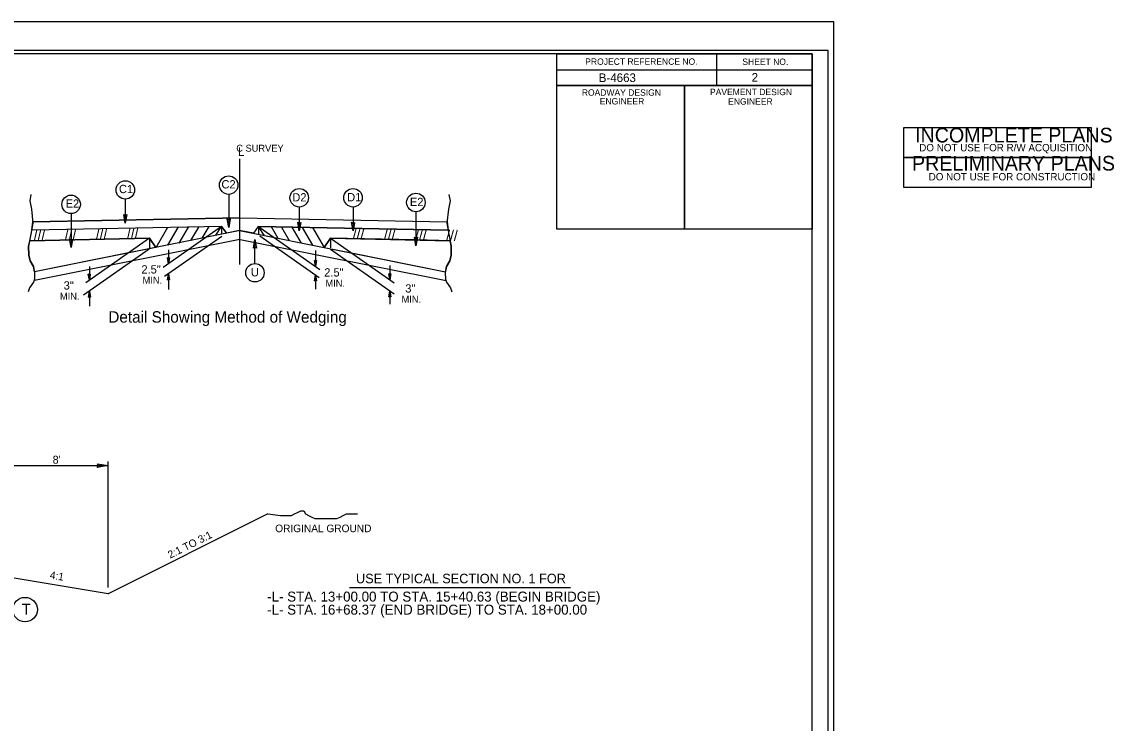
# Model space of a CAD drawing. Extents: x 693533 to 693723, y 486383 to 486493.
# Drawn here: x 693637.4 to 693723, y 486438.3 to 486493.3 of the extents above; entities that cross this region are included whole.
import ezdxf

# ---------------------------------------------------------------- set-up
doc = ezdxf.new("R2010")
doc.units = 0
for name, color, linetype in [('Old_Level_1', 7, 'Continuous'), ('Old_Level_11', 7, 'Continuous'), ('Old_Level_20', 7, 'Continuous'), ('Old_Level_21', 7, 'Continuous'), ('Old_Level_28', 7, 'Continuous'), ('Prop Dimension', 7, 'Continuous'), ('Sheet Cutting Line CELL', 7, 'Continuous'), ('Sheet Data Field CELL', 7, 'Continuous'), ('Sheet Plot Border Inside CELL', 7, 'Continuous'), ('Sheet Plot Border Outside CELL', 7, 'Continuous'), ('Sheet Sticker Incomplete CELL', 7, 'Continuous'), ('Sheet Sticker Preliminary CELL', 7, 'Continuous'), ('Sheet Typical CELL', 7, 'Continuous'), ('Typical Hinge Slope Arterial CELL', 7, 'Continuous'), ('Typical ID Circle CELL', 7, 'Continuous'), ('Typical Text ID Circle CELL', 7, 'Continuous'), ('Typical Text Label CELL', 7, 'Continuous')]:
    doc.layers.add(name, color=color, linetype=linetype)

msp = doc.modelspace()

# ---------------------------------------------------------------- linework, layer by layer
at = {"layer": 'Old_Level_1'}
for p, q in [((693648.814, 486477.181), (693647.891, 486475.6)), ((693649.624, 486477.198), (693648.807, 486475.796)), ((693650.426, 486477.214), (693649.693, 486475.957)), ((693651.234, 486477.212), (693650.627, 486476.171)), ((693652.049, 486477.254), (693651.519, 486476.346)), ((693656.057, 486477.18), (693660.77, 486473.879)), ((693656.944, 486477.254), (693657.474, 486476.346)), ((693657.759, 486477.212), (693658.366, 486476.171)), ((693658.567, 486477.214), (693659.3, 486475.957)), ((693659.369, 486477.198), (693660.186, 486475.796)), ((693660.18, 486477.181), (693661.089, 486475.623)), ((693647.394, 486476.339), (693638.01, 486476.151)), ((693638.01, 486476.151), (693647.394, 486476.339)), ((693654.49, 486476.253), (693638.377, 486473.029)), ((693647.394, 486476.339), (693642.411, 486472.85)), ((693647.904, 486475.622), (693647.394, 486476.339)), ((693647.394, 486476.339), (693647.394, 486475.52)), ((693647.394, 486476.339), (693647.903, 486475.623)), ((693653.064, 486476.472), (693648.588, 486473.337)), ((693654.503, 486476.253), (693670.654, 486473.022)), ((693656.05, 486476.538), (693660.717, 486473.271)), ((693661.599, 486476.339), (693661.089, 486475.623)), ((693661.09, 486475.623), (693661.599, 486476.339)), ((693661.599, 486476.339), (693670.984, 486476.151)), ((693661.599, 486476.339), (693661.599, 486475.578)), ((693668.292, 486476.205), (693661.599, 486476.339)), ((693661.675, 486476.286), (693666.589, 486472.844)), ((693647.39, 486475.495), (693642.239, 486471.87)), ((693647.394, 486475.521), (693645.76, 486475.194)), ((693647.903, 486475.623), (693647.394, 486475.521)), ((693648.896, 486475.431), (693648.896, 486474.343)), ((693660.425, 486475.369), (693660.425, 486474.121)), ((693661.089, 486475.623), (693663.234, 486475.194)), ((693661.599, 486475.479), (693666.581, 486471.989)), ((693670.984, 486476.151), (693668.292, 486476.205)), ((693645.76, 486475.194), (693638.382, 486473.719)), ((693648.896, 486474.343), (693648.811, 486474.82)), ((693648.896, 486474.758), (693648.811, 486474.82)), ((693648.896, 486474.343), (693648.823, 486474.811)), ((693648.835, 486474.802), (693648.896, 486474.343)), ((693648.896, 486474.343), (693648.847, 486474.794)), ((693648.86, 486474.785), (693648.896, 486474.343)), ((693648.896, 486474.343), (693648.872, 486474.776)), ((693648.884, 486474.767), (693648.896, 486474.343)), ((693648.896, 486474.343), (693648.98, 486474.82)), ((693648.98, 486474.82), (693648.896, 486474.758)), ((693648.968, 486474.811), (693648.896, 486474.343)), ((693648.896, 486474.343), (693648.955, 486474.802)), ((693648.943, 486474.794), (693648.896, 486474.343)), ((693648.896, 486474.343), (693648.931, 486474.785)), ((693648.919, 486474.776), (693648.896, 486474.343)), ((693648.896, 486474.343), (693648.908, 486474.767)), ((693648.896, 486474.758), (693648.896, 486474.343)), ((693660.425, 486474.121), (693660.341, 486474.599)), ((693660.425, 486474.537), (693660.341, 486474.599)), ((693660.425, 486474.121), (693660.353, 486474.59)), ((693660.365, 486474.581), (693660.425, 486474.121)), ((693660.425, 486474.121), (693660.377, 486474.572)), ((693660.389, 486474.563), (693660.425, 486474.121)), ((693660.425, 486474.121), (693660.401, 486474.554)), ((693660.413, 486474.546), (693660.425, 486474.121)), ((693660.425, 486474.121), (693660.51, 486474.599)), ((693660.51, 486474.599), (693660.425, 486474.537)), ((693660.497, 486474.59), (693660.425, 486474.121)), ((693660.425, 486474.121), (693660.485, 486474.581)), ((693660.473, 486474.572), (693660.425, 486474.121)), ((693660.425, 486474.121), (693660.461, 486474.563)), ((693660.449, 486474.554), (693660.425, 486474.121)), ((693660.425, 486474.121), (693660.437, 486474.546)), ((693660.425, 486474.537), (693660.425, 486474.121)), ((693663.234, 486475.194), (693670.611, 486473.719)), ((693642.692, 486474.131), (693642.692, 486473.046)), ((693666.252, 486474.209), (693666.252, 486473.081)), ((693642.692, 486473.046), (693642.607, 486473.523)), ((693642.692, 486473.462), (693642.607, 486473.523)), ((693642.692, 486473.046), (693642.619, 486473.515)), ((693642.632, 486473.505), (693642.692, 486473.046)), ((693642.692, 486473.046), (693642.644, 486473.497)), ((693642.656, 486473.488), (693642.692, 486473.046)), ((693642.692, 486473.046), (693642.668, 486473.479)), ((693642.68, 486473.471), (693642.692, 486473.046)), ((693642.692, 486473.046), (693642.776, 486473.523)), ((693642.776, 486473.523), (693642.692, 486473.462)), ((693642.764, 486473.515), (693642.692, 486473.046)), ((693642.692, 486473.046), (693642.752, 486473.505)), ((693642.74, 486473.497), (693642.692, 486473.046)), ((693642.692, 486473.046), (693642.728, 486473.488)), ((693642.716, 486473.479), (693642.692, 486473.046)), ((693642.692, 486473.046), (693642.704, 486473.471)), ((693642.692, 486473.462), (693642.692, 486473.046)), ((693648.896, 486473.553), (693648.811, 486473.075)), ((693648.811, 486473.075), (693648.896, 486473.137)), ((693648.823, 486473.085), (693648.896, 486473.553)), ((693648.896, 486473.553), (693648.835, 486473.093)), ((693648.847, 486473.103), (693648.896, 486473.553)), ((693648.896, 486473.553), (693648.86, 486473.111)), ((693648.872, 486473.12), (693648.896, 486473.553)), ((693648.896, 486473.553), (693648.884, 486473.129)), ((693648.896, 486473.553), (693648.896, 486472.327)), ((693648.896, 486473.553), (693648.98, 486473.075)), ((693648.896, 486473.137), (693648.896, 486473.553)), ((693648.908, 486473.129), (693648.896, 486473.553)), ((693648.896, 486473.553), (693648.919, 486473.12)), ((693648.931, 486473.111), (693648.896, 486473.553)), ((693648.896, 486473.553), (693648.943, 486473.103)), ((693648.955, 486473.093), (693648.896, 486473.553)), ((693648.896, 486473.553), (693648.968, 486473.085)), ((693648.896, 486473.137), (693648.98, 486473.075)), ((693660.425, 486473.475), (693660.341, 486472.998)), ((693660.341, 486472.998), (693660.425, 486473.06)), ((693660.353, 486473.007), (693660.425, 486473.475)), ((693660.425, 486473.475), (693660.365, 486473.016)), ((693660.377, 486473.025), (693660.425, 486473.475)), ((693660.425, 486473.475), (693660.389, 486473.034)), ((693660.401, 486473.042), (693660.425, 486473.475)), ((693660.425, 486473.475), (693660.413, 486473.051)), ((693660.425, 486473.475), (693660.425, 486472.359)), ((693660.425, 486473.475), (693660.51, 486472.998)), ((693660.425, 486473.06), (693660.425, 486473.475)), ((693660.437, 486473.051), (693660.425, 486473.475)), ((693660.425, 486473.475), (693660.449, 486473.042)), ((693660.461, 486473.034), (693660.425, 486473.475)), ((693660.425, 486473.475), (693660.473, 486473.025)), ((693660.485, 486473.016), (693660.425, 486473.475)), ((693660.425, 486473.475), (693660.497, 486473.007)), ((693660.425, 486473.06), (693660.51, 486472.998)), ((693666.252, 486473.081), (693666.167, 486473.558)), ((693666.252, 486473.497), (693666.167, 486473.558)), ((693666.252, 486473.081), (693666.179, 486473.549)), ((693666.191, 486473.541), (693666.252, 486473.081)), ((693666.252, 486473.081), (693666.203, 486473.533)), ((693666.215, 486473.523), (693666.252, 486473.081)), ((693666.252, 486473.081), (693666.227, 486473.515)), ((693666.239, 486473.505), (693666.252, 486473.081)), ((693666.252, 486473.081), (693666.336, 486473.558)), ((693666.336, 486473.558), (693666.252, 486473.497)), ((693666.323, 486473.549), (693666.252, 486473.081)), ((693666.252, 486473.081), (693666.311, 486473.541)), ((693666.299, 486473.533), (693666.252, 486473.081)), ((693666.252, 486473.081), (693666.287, 486473.523)), ((693666.275, 486473.515), (693666.252, 486473.081)), ((693666.252, 486473.081), (693666.263, 486473.505)), ((693666.252, 486473.497), (693666.252, 486473.081)), ((693642.692, 486472.187), (693642.607, 486471.71)), ((693642.62, 486471.719), (693642.692, 486472.187)), ((693642.692, 486472.187), (693642.632, 486471.728)), ((693642.644, 486471.737), (693642.692, 486472.187)), ((693642.692, 486472.187), (693642.656, 486471.746)), ((693642.668, 486471.754), (693642.692, 486472.187)), ((693642.692, 486472.187), (693642.68, 486471.762)), ((693642.692, 486472.187), (693642.692, 486471.027)), ((693642.692, 486472.187), (693642.776, 486471.71)), ((693642.692, 486471.772), (693642.692, 486472.187)), ((693642.704, 486471.762), (693642.692, 486472.187)), ((693642.692, 486472.187), (693642.716, 486471.754)), ((693642.728, 486471.746), (693642.692, 486472.187)), ((693642.692, 486472.187), (693642.74, 486471.737)), ((693642.752, 486471.728), (693642.692, 486472.187)), ((693642.692, 486472.187), (693642.764, 486471.719)), ((693666.252, 486472.221), (693666.167, 486471.743)), ((693666.179, 486471.752), (693666.252, 486472.221)), ((693666.252, 486472.221), (693666.191, 486471.761)), ((693666.203, 486471.77), (693666.252, 486472.221)), ((693666.252, 486472.221), (693666.215, 486471.779)), ((693666.227, 486471.788), (693666.252, 486472.221)), ((693666.252, 486472.221), (693666.239, 486471.796)), ((693666.252, 486472.221), (693666.252, 486471.173)), ((693666.252, 486472.221), (693666.336, 486471.743)), ((693666.252, 486471.806), (693666.252, 486472.221)), ((693666.263, 486471.796), (693666.252, 486472.221)), ((693666.252, 486472.221), (693666.275, 486471.788)), ((693666.287, 486471.779), (693666.252, 486472.221)), ((693666.252, 486472.221), (693666.299, 486471.77)), ((693666.311, 486471.761), (693666.252, 486472.221)), ((693666.252, 486472.221), (693666.323, 486471.752)), ((693642.607, 486471.71), (693642.692, 486471.772)), ((693642.692, 486471.772), (693642.776, 486471.71)), ((693666.167, 486471.743), (693666.252, 486471.806)), ((693666.252, 486471.806), (693666.336, 486471.743))]:
    msp.add_line(p, q, dxfattribs=at)
for points in [[(693638.109, 486479.764), (693638.023, 486479.288), (693638.153, 486478.612), (693638.268, 486477.517), (693638.109, 486476.653), (693637.923, 486475.717), (693637.937, 486475.011), (693638.052, 486474.565), (693638.312, 486474.118), (693638.398, 486473.629), (693638.383, 486473.139), (693638.297, 486472.908), (693637.995, 486472.447), (693637.894, 486472.131)], [(693670.883, 486479.764), (693670.97, 486479.288), (693670.84, 486478.612), (693670.725, 486477.517), (693670.883, 486476.653), (693671.071, 486475.717), (693671.056, 486475.011), (693670.941, 486474.565), (693670.682, 486474.118), (693670.596, 486473.629), (693670.609, 486473.139), (693670.696, 486472.908), (693670.998, 486472.447), (693671.099, 486472.131)], [(693638.382, 486473.719), (693638.312, 486474.118), (693638.052, 486474.565), (693637.937, 486475.011), (693637.923, 486475.717), (693638.009, 486476.151)], [(693670.611, 486473.719), (693670.682, 486474.118), (693670.941, 486474.565), (693671.056, 486475.011), (693671.071, 486475.717), (693670.984, 486476.151)]]:
    msp.add_lwpolyline(points, dxfattribs=at)
at = {"layer": 'Old_Level_11'}
for p, q in [((693654.497, 486474.291), (693654.497, 486482.563)), ((693653.615, 486479.786), (693653.615, 486477.182)), ((693654.497, 486474.291), (693654.497, 486479.941)), ((693645.507, 486479.406), (693645.507, 486477.532)), ((693659.143, 486478.79), (693659.143, 486476.916)), ((693663.361, 486478.79), (693663.361, 486476.916)), ((693654.496, 486477.945), (693638.261, 486477.621)), ((693638.261, 486477.621), (693654.496, 486477.945)), ((693641.256, 486478.274), (693641.256, 486475.609)), ((693654.496, 486477.945), (693670.733, 486477.621)), ((693654.498, 486477.945), (693670.733, 486477.621)), ((693668.292, 486478.422), (693668.292, 486475.757)), ((693638.168, 486476.969), (693638.261, 486477.621)), ((693653.072, 486477.267), (693638.168, 486476.969)), ((693653.072, 486477.267), (693638.168, 486476.969)), ((693653.053, 486477.255), (693648.479, 486474.051)), ((693652.611, 486476.572), (693653.051, 486477.261)), ((693653.051, 486477.261), (693653.051, 486476.695)), ((693653.437, 486476.732), (693653.072, 486477.267)), ((693653.072, 486477.249), (693653.437, 486476.732)), ((693655.933, 486477.267), (693655.556, 486476.732)), ((693655.933, 486477.267), (693655.556, 486476.732)), ((693655.909, 486477.255), (693655.932, 486477.254)), ((693655.933, 486477.267), (693670.826, 486476.969)), ((693670.826, 486476.969), (693655.933, 486477.267)), ((693656.383, 486476.572), (693655.942, 486477.261)), ((693655.942, 486477.261), (693655.942, 486476.638)), ((693670.733, 486477.621), (693670.826, 486476.969)), ((693654.521, 486476.947), (693638.382, 486473.719)), ((693654.472, 486476.947), (693653.437, 486476.732)), ((693654.472, 486476.947), (693670.611, 486473.719)), ((693655.556, 486476.732), (693654.472, 486476.947)), ((693655.671, 486474.362), (693655.671, 486476.236))]:
    msp.add_line(p, q, dxfattribs=at)
for points in [[(693645.622, 486478.204), (693645.507, 486477.532), (693645.387, 486478.207), (693645.507, 486478.122)], [(693653.731, 486477.854), (693653.615, 486477.182), (693653.496, 486477.858), (693653.615, 486477.772)], [(693659.258, 486477.587), (693659.143, 486476.916), (693659.023, 486477.591), (693659.143, 486477.505)], [(693663.477, 486477.587), (693663.361, 486476.916), (693663.242, 486477.591), (693663.361, 486477.505)], [(693641.372, 486476.28), (693641.256, 486475.609), (693641.137, 486476.284), (693641.256, 486476.198)], [(693655.556, 486475.565), (693655.671, 486476.236), (693655.791, 486475.561), (693655.671, 486475.647)], [(693668.407, 486476.429), (693668.292, 486475.757), (693668.172, 486476.432), (693668.292, 486476.347)]]:
    msp.add_lwpolyline(points, close=True, dxfattribs=at)
for centre in [(693645.507, 486480.132), (693653.615, 486480.511), (693641.256, 486478.999), (693659.143, 486479.515), (693663.361, 486479.515), (693668.291, 486479.147), (693655.671, 486473.637)]:
    msp.add_circle(centre, 0.725, dxfattribs=at)
at = {"layer": 'Old_Level_28'}
msp.add_lwpolyline([(693643.315, 486458.657), (693644.159, 486458.512), (693643.31, 486458.362), (693643.418, 486458.512)], close=True, dxfattribs=at)
at = {"layer": 'Prop Dimension'}
for p, q in [((693636.159, 486458.512), (693644.159, 486458.512)), ((693644.159, 486448.941), (693644.159, 486458.824))]:
    msp.add_line(p, q, dxfattribs=at)
at = {"layer": 'Sheet Cutting Line CELL'}
msp.add_line((693701.059, 486493.314), (693532.659, 486493.314), dxfattribs=at)
at = {"layer": 'Sheet Plot Border Inside CELL'}
msp.add_lwpolyline([(693700.609, 486491.069), (693533.959, 486491.069), (693533.959, 486385.559), (693700.609, 486385.559)], close=True, dxfattribs=at)
at = {"layer": 'Sheet Plot Border Outside CELL'}
msp.add_lwpolyline([(693701.059, 486493.314), (693532.659, 486493.314), (693532.659, 486383.314), (693701.059, 486383.314)], close=True, dxfattribs=at)
at = {"layer": 'Sheet Sticker Incomplete CELL'}
msp.add_lwpolyline([(693706.541, 486482.684), (693706.541, 486485.034), (693721.241, 486485.034), (693721.241, 486482.684)], close=True, dxfattribs=at)
at = {"layer": 'Sheet Sticker Preliminary CELL'}
msp.add_lwpolyline([(693706.541, 486480.334), (693706.541, 486482.684), (693721.241, 486482.684), (693721.241, 486480.334)], close=True, dxfattribs=at)
at = {"layer": 'Sheet Typical CELL'}
for p, q in [((693691.859, 486490.809), (693691.859, 486488.309)), ((693679.354, 486489.559), (693699.359, 486489.559)), ((693689.359, 486488.309), (693689.359, 486477.064))]:
    msp.add_line(p, q, dxfattribs=at)
for points in [[(693699.359, 486490.814), (693549.359, 486490.814), (693549.359, 486385.814), (693699.359, 486385.814)], [(693679.354, 486490.814), (693699.359, 486490.814), (693699.359, 486488.309), (693679.354, 486488.309)], [(693679.354, 486488.309), (693689.359, 486488.309), (693689.359, 486477.059), (693679.354, 486477.059)], [(693689.359, 486488.309), (693699.359, 486488.309), (693699.359, 486477.059), (693689.359, 486477.059)]]:
    msp.add_lwpolyline(points, close=True, dxfattribs=at)
at = {"layer": 'Typical Hinge Slope Arterial CELL'}
for p, q in [((693656.679, 486454.723), (693644.159, 486448.463)), ((693644.159, 486448.463), (693636.159, 486449.797))]:
    msp.add_line(p, q, dxfattribs=at)
msp.add_lwpolyline([(693656.679, 486454.723), (693657.664, 486454.601), (693657.91, 486454.601), (693658.28, 486454.601), (693658.527, 486454.601), (693658.773, 486454.723), (693659.02, 486454.847), (693659.266, 486454.971), (693659.512, 486454.971), (693659.636, 486454.723), (693659.882, 486454.601), (693660.129, 486454.477), (693660.375, 486454.354), (693660.621, 486454.354), (693660.868, 486454.354), (693661.114, 486454.354), (693661.361, 486454.354), (693661.607, 486454.354), (693661.853, 486454.354), (693662.1, 486454.354), (693662.346, 486454.477), (693662.592, 486454.601), (693662.839, 486454.723), (693663.209, 486454.723), (693663.455, 486454.723), (693663.701, 486454.723)], dxfattribs=at)
at = {"layer": 'Typical ID Circle CELL'}
msp.add_circle((693637.648, 486447.219), 0.962, dxfattribs=at)
at = {"layer": 'Typical Text Label CELL'}
msp.add_line((693663.083, 486448.946), (693680.406, 486448.946), dxfattribs=at)

# ---------------------------------------------------------------- texts
at = {"layer": 'Old_Level_1'}
for s, height, rotation, p in [('C SURVEY ', 0.5424, 360, (693654.21, 486483.132)), ('L', 0.678, 360, (693654.341, 486482.785)), ('/// ', 0.8139, 1.14453, (693643.205, 486476.263)), ('/// ', 0.8139, 1.14629, (693645.646, 486476.313)), ('/// ', 0.8139, 358.85527, (693663.347, 486476.313)), ('/// ', 0.8139, 358.85361, (693665.788, 486476.263)), ('/// ', 0.8142, 1.14473, (693638.333, 486476.162)), ('/// ', 0.8142, 1.14639, (693640.766, 486476.191)), ('/// ', 0.8142, 358.85537, (693668.227, 486476.191)), ('/// ', 0.8142, 358.85371, (693670.66, 486476.162))]:
    msp.add_text(s, height=height, rotation=rotation, dxfattribs=at).set_placement(p)
at = {"layer": 'Old_Level_20'}
for s, height, p in [('C1', 0.6491, (693645.011, 486479.88)), ('C2', 0.6491, (693653.048, 486480.249)), ('D2', 0.6491, (693658.604, 486479.228)), ('D1', 0.6491, (693662.905, 486479.239)), ('E2', 0.6491, (693640.828, 486478.737)), ('E2', 0.6491, (693667.822, 486478.865)), ('2.5"', 0.6491, (693646.769, 486473.576)), ('U', 0.649, (693655.354, 486473.35)), ('2.5"', 0.6491, (693661.105, 486473.34)), ('3"', 0.6491, (693667.46, 486472.082))]:
    msp.add_text(s, height=height, rotation=360, dxfattribs=at).set_placement(p)
msp.add_text('3"', height=0.6491, dxfattribs=at).set_placement((693640.675, 486472.318))
at = {"layer": 'Old_Level_21'}
for s, height, p in [('MIN.', 0.5424, (693646.865, 486472.778)), ('MIN.', 0.5424, (693661.2, 486472.542)), ('MIN.', 0.5424, (693640.385, 486471.52)), ('MIN.', 0.5424, (693667.17, 486471.284)), ('Detail Showing Method of Wedging', 0.89531, (693644.177, 486469.724))]:
    msp.add_text(s, height=height, rotation=360, dxfattribs=at).set_placement(p)
at = {"layer": 'Prop Dimension'}
msp.add_text("8'", height=0.6249, dxfattribs=at).set_placement((693639.812, 486458.663))
at = {"layer": 'Sheet Data Field CELL'}
for s, p in [('B-4663   ', (693682.633, 486488.594)), ('2  ', (693694.62, 486488.624))]:
    msp.add_text(s, height=0.675, dxfattribs=at).set_placement(p)
at = {"layer": 'Sheet Sticker Incomplete CELL'}
for s, height, p in [('INCOMPLETE PLANS', 1.152, (693707.436, 486483.854)), ('DO NOT USE FOR R/W ACQUISITION', 0.576, (693707.761, 486483.159))]:
    msp.add_text(s, height=height, dxfattribs=at).set_placement(p)
at = {"layer": 'Sheet Sticker Preliminary CELL'}
for s, height, p in [('PRELIMINARY PLANS', 1.152, (693707.191, 486481.649)), ('DO NOT USE FOR CONSTRUCTION', 0.576, (693708.501, 486480.879))]:
    msp.add_text(s, height=height, dxfattribs=at).set_placement(p)
at = {"layer": 'Sheet Typical CELL'}
for s, height, p in [('PROJECT REFERENCE NO.', 0.50001, (693681.574, 486489.944)), ('SHEET NO.', 0.5, (693693.889, 486489.934)), ('ROADWAY DESIGN', 0.50001, (693681.304, 486487.519)), ('PAVEMENT DESIGN', 0.50001, (693691.354, 486487.564)), ('ENGINEER', 0.5, (693682.709, 486486.834)), ('ENGINEER', 0.5, (693692.774, 486486.819))]:
    msp.add_text(s, height=height, dxfattribs=at).set_placement(p)
at = {"layer": 'Typical Hinge Slope Arterial CELL'}
for s, rotation, p in [('2:1 TO 3:1', 26.56505, (693649.024, 486451.208)), ('4:1', 350.53768, (693639.552, 486449.656))]:
    msp.add_text(s, height=0.5937, rotation=rotation, dxfattribs=at).set_placement(p)
msp.add_text('ORIGINAL GROUND', height=0.59365, dxfattribs=at).set_placement((693657.262, 486453.291))
at = {"layer": 'Typical Text ID Circle CELL'}
msp.add_text('T', height=0.861, dxfattribs=at).set_placement((693637.388, 486446.823))
at = {"layer": 'Typical Text Label CELL'}
for s, height, p in [('USE TYPICAL SECTION NO. 1 FOR', 0.74597, (693663.595, 486449.284)), ('-L- STA. 13+00.00 TO STA. 15+40.63 (BEGIN BRIDGE)', 0.78125, (693656.635, 486447.849)), ('-L- STA. 16+68.37 (END BRIDGE) TO STA. 18+00.00 ', 0.78125, (693656.635, 486446.825))]:
    msp.add_text(s, height=height, dxfattribs=at).set_placement(p)

doc.saveas('drawing.dxf')
